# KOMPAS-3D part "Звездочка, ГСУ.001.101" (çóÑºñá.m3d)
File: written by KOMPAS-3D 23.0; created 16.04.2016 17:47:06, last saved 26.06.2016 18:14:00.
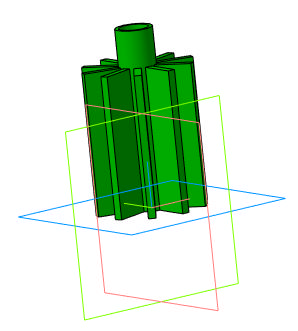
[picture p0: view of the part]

Document properties: Автор: Аня; Полное имя файла: ..\Чертежи\ГСУ.001.101 - Звездочка.cdw

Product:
- Part/product: Звездочка  | designation ГСУ.001.101
    Масса: 0.070244
    Форматы листов документа: A4

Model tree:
1. Эскиз:1
2. Операция выдавливания:1
     Расстояние 1 = 38
3. Эскиз:2
4. Операция выдавливания:2
     Расстояние 2 = 38
5. Массив по концентрической сетке:1  (with: Операция выдавливания:2, Эскиз:2)  (10 pattern instances)
     Шаг 2 = 360
6. Эскиз:3
7. Операция выдавливания:3
     Расстояние 1 = 10

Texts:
  ГСУ.001.101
